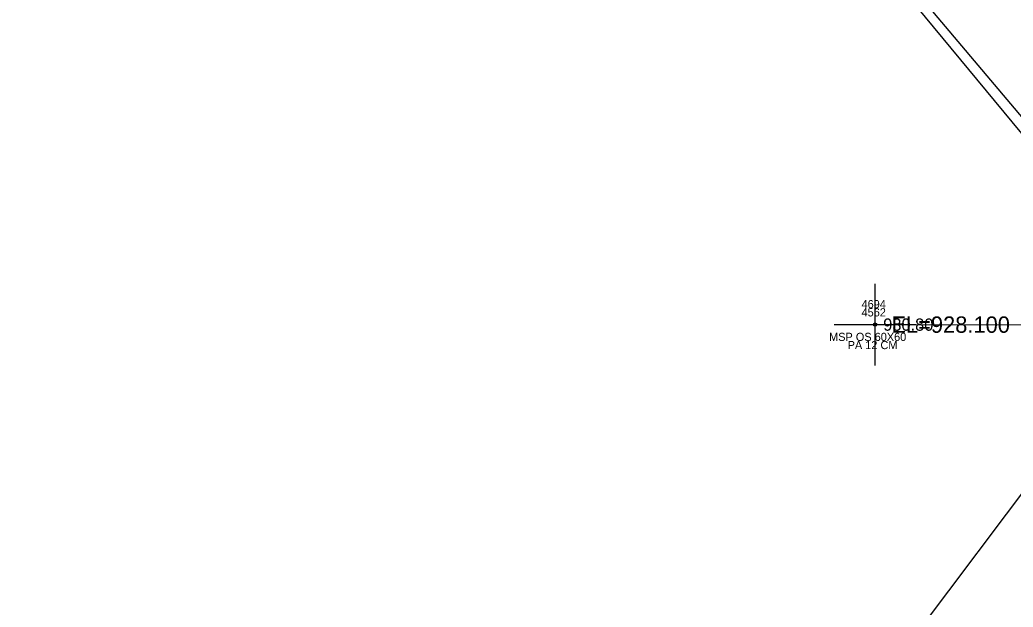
# Model space of a CAD drawing. Extents: x 1575382 to 1578175, y 1099175 to 1101955.
# Drawn here: x 1576232.8 to 1576354.3, y 1100005.4 to 1100077.2 of the extents above; entities that cross this region are included whole.
import ezdxf

# ---------------------------------------------------------------- set-up
doc = ezdxf.new("R2010")
doc.units = 0
for name, color, linetype in [('RD_EX_Conc', 7, 'Continuous'), ('RD_EX_DR_Pipe', 7, 'Continuous'), ('RD_EX_DR_Pipe_txCode', 7, 'Continuous'), ('RD_EX_Misc', 7, 'Continuous'), ('RD_EX_Misc_txCode', 7, 'Continuous'), ('RD_EX_Road', 7, 'Continuous'), ('RD_EX_TX_Misc_ELEV', 7, 'Continuous'), ('RD_SMD_Locator', 7, 'Continuous'), ('RD_TX_Pipe_ElevEX', 7, 'Continuous')]:
    doc.layers.add(name, color=color, linetype=linetype)

msp = doc.modelspace()

# ---------------------------------------------------------------- linework, layer by layer
at = {"layer": 'RD_EX_Conc'}
msp.add_lwpolyline([(1576370.77, 1100044.65), (1576358.48, 1100059.51), (1576327.45, 1100097.03), (1576315.3, 1100111.52), (1576315.3, 1100111.52), (1576311.1, 1100116.47)], dxfattribs=at)
at = {"layer": 'RD_EX_DR_Pipe'}
for p in [(1576264.57, 1099898.53), (1576337.38, 1100039.92)]:
    msp.add_line(p, (1576370.84, 1100039.87), dxfattribs=at)
at = {"layer": 'RD_EX_Misc'}
for p, q in [((1576337.38, 1100034.92), (1576337.38, 1100044.92)), ((1576332.38, 1100039.92), (1576342.38, 1100039.92))]:
    msp.add_line(p, q, dxfattribs=at)
at = {"layer": 'RD_EX_Road'}
msp.add_lwpolyline([(1576526.76, 1099857.36), (1576527.6, 1099858), (1576488.54, 1099905.39), (1576460.88, 1099939.06), (1576418.27, 1099989.97), (1576392.95, 1100020.59), (1576359.55, 1100060.38), (1576328.02, 1100097.72), (1576316.02, 1100112.1), (1576316.51, 1100112.71), (1576297.48, 1100135.6), (1576269.79, 1100169.04), (1576232.76, 1100213.96)], dxfattribs=at)
at = {"layer": 'RD_SMD_Locator'}
for radius in [0.2, 0.15]:
    msp.add_circle((1576337.38, 1100039.92), radius, dxfattribs=at)

# ---------------------------------------------------------------- texts
at = {"layer": 'RD_EX_DR_Pipe_txCode'}
for s, p in [('4694', (1576335.73, 1100041.92)), ('PA 12 CM', (1576334.03, 1100036.92))]:
    msp.add_text(s, height=1, dxfattribs=at).set_placement(p)
at = {"layer": 'RD_EX_Misc_txCode'}
for s, p in [('4562', (1576335.73, 1100040.92)), ('MSP OS 60X60', (1576331.76, 1100037.92))]:
    msp.add_text(s, height=1, dxfattribs=at).set_placement(p)
at = {"layer": 'RD_EX_TX_Misc_ELEV'}
msp.add_text('930.80', height=1.5, dxfattribs=at).set_placement((1576338.38, 1100039.17))
at = {"layer": 'RD_TX_Pipe_ElevEX'}
msp.add_text('EL=928.100', height=2, dxfattribs=at).set_placement((1576339.38, 1100038.92))

doc.saveas('drawing.dxf')
